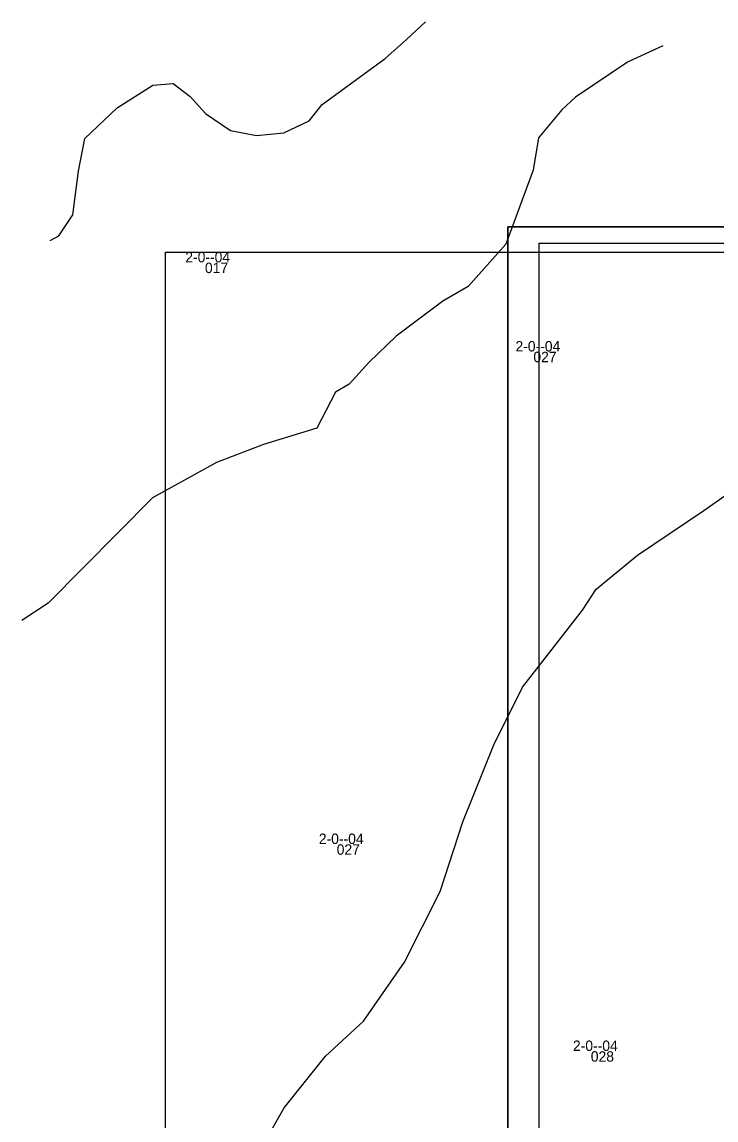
# Model space of a CAD drawing. Extents: x -557103 to -548162, y -1041918 to -1033974.
# Drawn here: x -556804 to -554667, y -1037353 to -1033974 of the extents above; entities that cross this region are included whole.
import ezdxf

# ---------------------------------------------------------------- set-up
doc = ezdxf.new("R2010")
doc.units = 0
for name, color, linetype in [('body1', 7, 'Continuous'), ('Rámeček', 7, 'Continuous'), ('Vrstva 16', 7, 'Continuous'), ('Vrstva 63', 7, 'Continuous')]:
    doc.layers.add(name, color=color, linetype=linetype)

msp = doc.modelspace()

# ---------------------------------------------------------------- linework, layer by layer
at = {"layer": 'body1'}
msp.add_lwpolyline([(-550469.3, -1040018.6), (-555211.6, -1040018.6), (-555211.6, -1034654.7), (-550469.3, -1034654.7)], close=True, dxfattribs=at)
at = {"layer": 'Rámeček'}
for points in [[(-555307.9, -1039662.1), (-550042, -1039662.1), (-550042, -1034604.4), (-555307.9, -1034604.4)], [(-555307.9, -1034604.4), (-548161.9, -1034604.4), (-548161.9, -1039661.8), (-555307.9, -1039661.8)]]:
    msp.add_lwpolyline(points, close=True, dxfattribs=at)
at = {"layer": 'Vrstva 16'}
for points in [[(-556717.2, -1034647.2), (-556689.8, -1034632.3), (-556647.5, -1034567.5), (-556630, -1034432.9), (-556610.1, -1034333.2), (-556510.4, -1034238.4), (-556400.8, -1034168.6), (-556338.5, -1034163.7), (-556286.2, -1034203.5), (-556238.9, -1034255.9), (-556161.6, -1034308.2), (-556081.9, -1034323.2), (-555997.2, -1034315.7), (-555920, -1034278.3), (-555880.1, -1034228.5), (-555685.8, -1034086.4), (-555621, -1034029.1), (-555561.2, -1033974.2)], [(-554831, -1034047.5), (-554939.2, -1034097.5), (-555100.1, -1034205.7), (-555141.7, -1034244.6), (-555213.9, -1034330.7), (-555230.5, -1034430.6), (-555313.8, -1034658.2), (-555430.3, -1034788.7), (-555508, -1034833.1), (-555652.3, -1034941.4), (-555735.6, -1035021.9), (-555796.6, -1035088.5), (-555838.2, -1035113.5), (-555896.5, -1035224.5), (-556060.2, -1035274.5), (-556204.5, -1035330), (-556401.5, -1035438.3), (-556723.4, -1035763.1), (-556803.9, -1035815.8)], [(-556114, -1037521.2), (-555996.9, -1037316), (-555869.8, -1037156.5), (-555752.7, -1037049.3), (-555625.7, -1036867.3), (-555516, -1036650.5), (-555446.3, -1036436.1), (-555351.6, -1036199.3), (-555262.9, -1036021.1), (-555200.6, -1035941.4), (-555078.6, -1035784.3), (-555036.2, -1035719.5), (-554909.1, -1035614.8), (-554704.8, -1035477.7), (-554572.8, -1035385.5)]]:
    msp.add_lwpolyline(points, dxfattribs=at)
at = {"layer": 'Vrstva 63'}
msp.add_lwpolyline([(-550519.3, -1039635.9), (-556362.3, -1039635.9), (-556362.3, -1034682.3), (-550519.3, -1034682.3)], close=True, dxfattribs=at)

# ---------------------------------------------------------------- texts
at = {"layer": 'Vrstva 16'}
for s, p in [('2-0--04', (-556301, -1034714)), ('017', (-556240.5, -1034747)), ('2-0--04', (-555284.5, -1034988.2)), ('027', (-555229.4, -1035021.2)), ('2-0--04', (-555889.9, -1036503.9)), ('027', (-555834.9, -1036536.9)), ('2-0--04', (-555107.6, -1037140.8)), ('028', (-555052.6, -1037173.8))]:
    msp.add_text(s, height=32, dxfattribs=at).set_placement(p)

doc.saveas('drawing.dxf')
